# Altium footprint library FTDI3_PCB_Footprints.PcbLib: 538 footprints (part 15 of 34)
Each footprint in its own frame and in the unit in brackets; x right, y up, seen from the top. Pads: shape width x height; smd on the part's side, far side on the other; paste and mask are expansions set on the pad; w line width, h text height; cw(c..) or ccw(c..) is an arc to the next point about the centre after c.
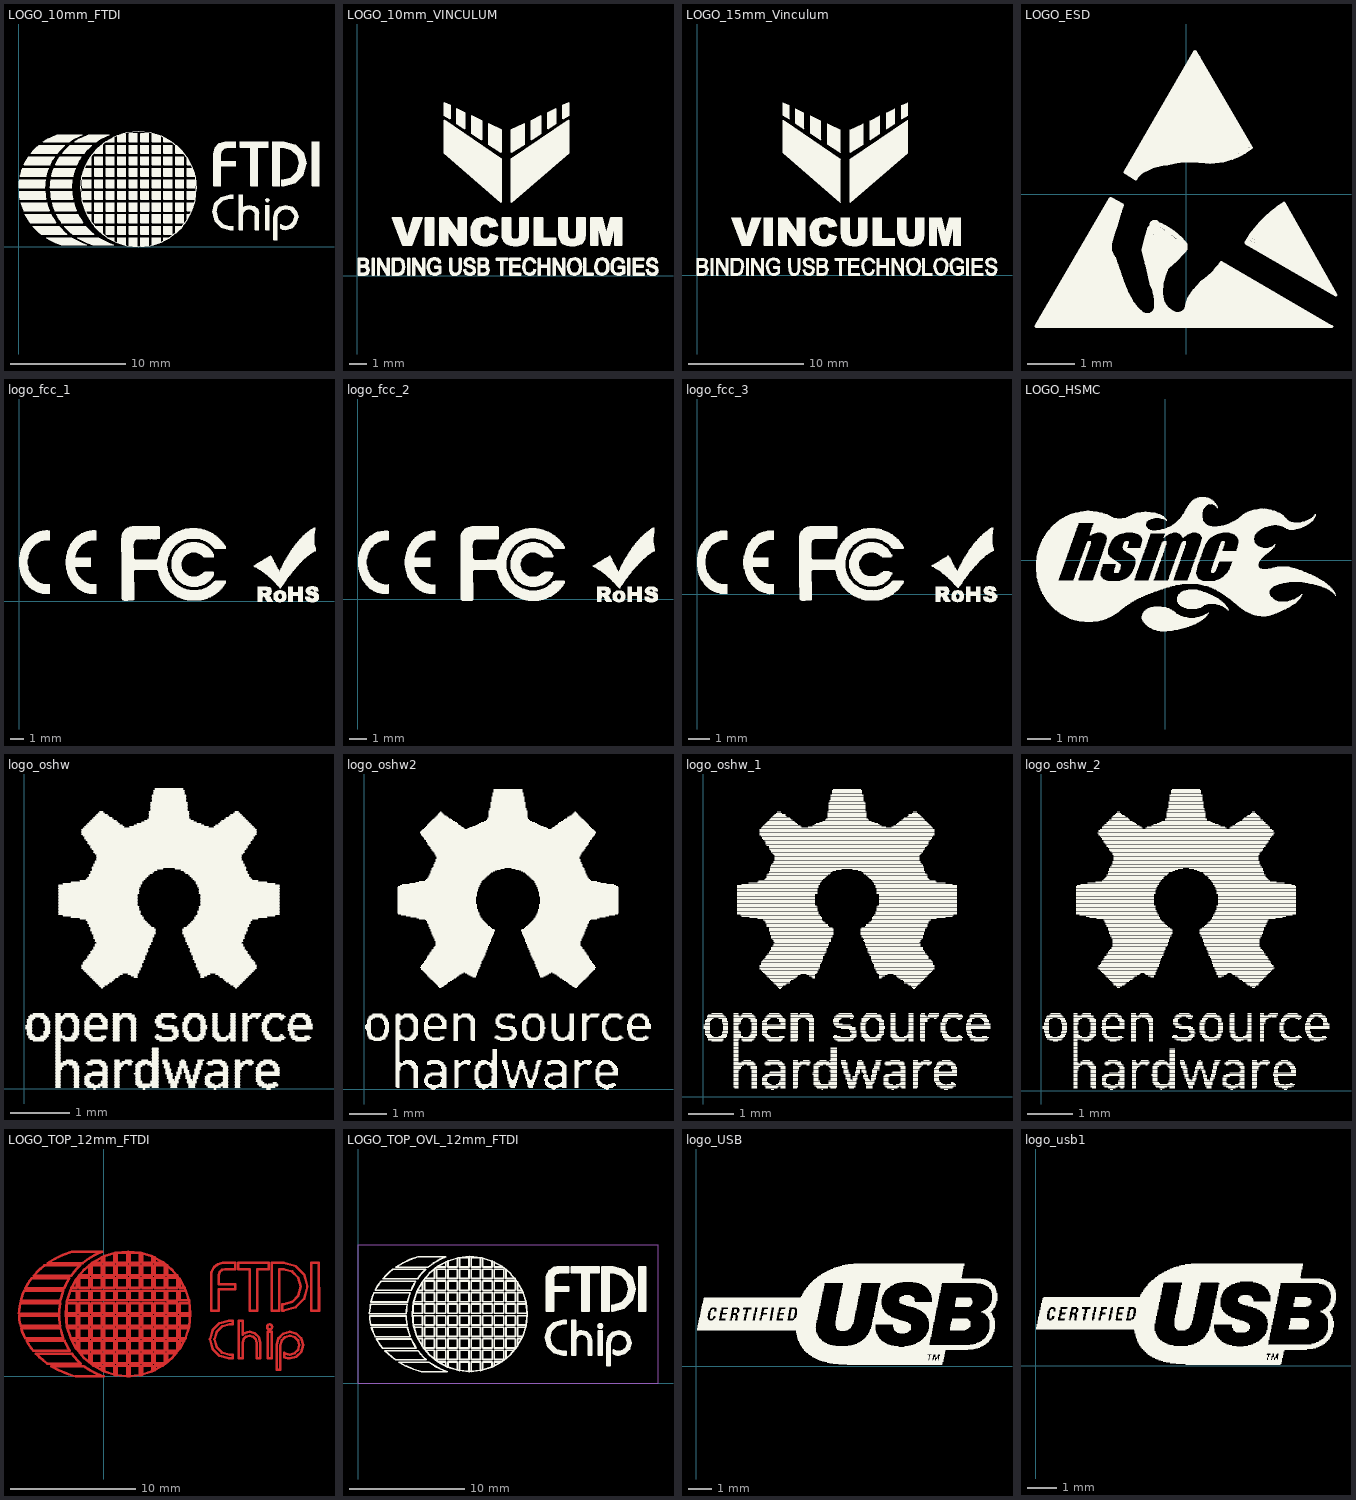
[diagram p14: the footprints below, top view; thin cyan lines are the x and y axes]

## LOGO_10mm_FTDI [mm]
Top Overlay:
  drawing of 816 lines, arcs and shapes, not listed

## LOGO_10mm_VINCULUM [mm]
Top Overlay:
  drawing of 1161 lines, arcs and shapes, not listed

## LOGO_15mm_Vinculum [mm] "Logo, Vinculum, 15mm Height"
Top Overlay:
  drawing of 1150 lines, arcs and shapes, not listed

## LOGO_ESD [mm]
Top Overlay:
  drawing of 1029 lines, arcs and shapes, not listed

## logo_fcc_1 [mm]
Top Overlay:
  drawing of 1453 lines, arcs and shapes, not listed

## logo_fcc_2 [mm]
Top Overlay:
  drawing of 1141 lines, arcs and shapes, not listed

## logo_fcc_3 [mm]
Top Overlay:
  drawing of 910 lines, arcs and shapes, not listed

## LOGO_HSMC [mm]
Top Overlay:
  drawing of 2170 lines, arcs and shapes, not listed

## logo_oshw [mm]
Top Overlay:
  drawing of 812 lines, arcs and shapes, not listed

## logo_oshw2 [mm]
Top Overlay:
  drawing of 1256 lines, arcs and shapes, not listed

## logo_oshw_1 [mm]
Top Overlay:
  drawing of 1060 lines, arcs and shapes, not listed

## logo_oshw_2 [mm]
Top Overlay:
  drawing of 1071 lines, arcs and shapes, not listed

## LOGO_TOP_12mm_FTDI [mm]
Top Layer:
  lines w0.2: -2.955,4.121 -2.955,4.857 -2.154,4.857 -2.154,4.059 ; -2.955,5.795 -2.955,5.062 -2.154,5.062 -2.154,5.867 -2.944,5.867 ; -2.944,4.061 -2.154,4.059 ; -2.908,6.072 -2.154,6.072 -2.154,6.869 -2.656,6.869 ; -2.899,3.861 -2.154,3.858 -2.154,3.053 -2.62,3.053 ; -2.57,7.07 -2.154,7.07 -2.154,7.809 ; -2.527,2.855 -2.154,2.855 -2.154,2.208 ; -2.174,4.062 -2.168,4.061 -2.16,4.059 -2.154,4.059 ; -1.951,8.082 -1.147,8.082 -1.147,8.88 ; -1.886,1.85 -1.147,1.85 -1.147,1.121 ; -0.898,9.084 -0.141,9.084 -0.141,9.513 ; -0.765,0.843 -0.141,0.843 -0.141,0.496 ; 0.056,0.409 0.056,0.843 0.863,0.843 0.863,0.151 ; 0.056,9.601 0.056,9.084 0.863,9.084 0.863,9.859 ; 1.062,0.105 1.062,0.843 1.868,0.843 1.868,0.024 ; 2.068,0.026 2.068,0.843 2.874,0.843 2.874,0.11 ; 3.076,0.151 3.076,0.843 3.879,0.843 3.879,0.409 ; 3.076,9.859 3.076,9.084 3.879,9.084 3.879,9.595 ; 4.073,0.498 4.073,0.843 4.686,0.843 ; 4.073,9.508 4.073,9.084 4.809,9.084 ; 5.079,1.13 5.079,1.85 5.8,1.85 ; 5.079,8.88 5.079,8.082 5.872,8.082 ; 6.081,2.22 6.081,2.855 6.446,2.855 ; 6.081,7.791 6.081,7.07 6.488,7.07 ; 6.542,3.053 6.081,3.053 6.081,3.858 6.806,3.858 ; 6.575,6.869 6.081,6.869 6.081,6.072 6.824,6.072 ; 6.846,4.059 6.081,4.059 6.081,4.857 6.891,4.857 6.891,4.326 ; 6.847,5.867 6.081,5.867 6.081,5.062 6.891,5.062 6.891,5.694 ; 9.197,8.111 9.265,8.347 9.447,8.515 9.705,8.579 10.507,8.579 10.508,9.084 9.513,9.086 9.139,8.979 8.822,8.727 8.627,8.382 8.611,8.316 8.601,8.25 8.597,8.187 8.6,5.263 9.202,5.263 9.202,6.974 10.507,6.974 10.507,7.375 9.202,7.375 9.197,8.111 ; 9.197,8.111 9.197,8.11 9.197,8.113 9.197,8.111 ; 10.807,1.445 10.818,1.445 10.807,1.445 ; 10.807,1.445 10.807,4.462 11.111,4.462 11.111,3.35 11.276,3.461 11.464,3.533 11.662,3.559 12.094,3.442 12.401,3.137 12.518,2.706 12.518,1.445 12.216,1.445 12.216,2.709 12.14,2.986 11.941,3.181 11.662,3.256 11.384,3.182 11.186,2.987 11.111,2.71 11.111,1.445 10.807,1.445 ; 14.387,9.085 13.421,9.077 13.421,5.261 14.026,5.264 14.026,8.58 14.389,8.579 15.066,8.388 15.551,7.887 15.737,7.18 15.553,6.47 15.072,5.965 14.396,5.772 14.29,5.772 14.29,5.27 14.393,5.27 15.348,5.532 16.028,6.219 16.287,7.183 16.026,8.143 15.343,8.825 14.386,9.085 ; 14.386,9.085 14.387,9.085 ; 14.387,9.085 14.387,9.085 ; 14.387,9.085 14.387,9.085 ; -6.764,5.041 -6.758,5.041 -6.746,5.041 -6.739,5.041 -3.559,5.027 -3.546,5.305 -3.517,5.588 -3.477,5.853 -6.657,5.853 -6.696,5.596 -6.742,5.311 -6.764,5.041 ; -6.742,4.841 -6.726,4.571 -6.686,4.303 -6.636,4.047 -3.488,4.047 -3.525,4.298 -3.556,4.576 -3.567,4.841 -6.742,4.841 ; -6.624,6.049 -6.554,6.314 -6.457,6.592 -6.353,6.857 -3.227,6.857 -3.316,6.592 -3.4,6.314 -3.461,6.049 -6.624,6.049 ; -6.576,3.846 -6.49,3.577 -6.386,3.294 -6.267,3.04 -3.211,3.04 -3.304,3.294 -3.385,3.577 -3.45,3.846 -6.576,3.846 ; -6.254,7.06 -6.107,7.326 -5.93,7.603 -5.748,7.854 -2.744,7.854 -2.886,7.603 -3.02,7.326 -3.136,7.06 -6.254,7.06 ; -6.158,2.839 -6.003,2.572 -5.808,2.291 -5.605,2.037 -2.694,2.037 -2.851,2.295 -2.998,2.567 -3.126,2.839 -6.158,2.839 ; -5.583,8.051 -5.328,8.334 -5.034,8.62 -4.73,8.875 -1.883,8.875 -2.134,8.621 -2.377,8.336 -2.588,8.055 -5.583,8.051 ; -5.42,1.827 -2.548,1.827 -2.322,1.544 -2.083,1.275 -1.831,1.031 -4.502,1.031 -4.818,1.279 -5.138,1.552 -5.42,1.827 ; -4.473,9.062 -3.878,9.419 -3.224,9.732 -2.546,9.979 -0.131,9.979 -0.676,9.732 -1.197,9.419 -1.676,9.062 -4.473,9.062 ; -4.185,0.821 -3.576,0.49 -2.919,0.208 -2.243,0 0,0 -0.545,0.213 -1.093,0.498 -1.581,0.821 -4.185,0.821 ; -3.035,5 -2.934,6.002 -2.643,6.936 -2.182,7.782 -1.573,8.52 -0.835,9.13 0.012,9.59 0.946,9.881 1.948,9.983 2.951,9.881 3.886,9.59 4.732,9.13 5.47,8.52 6.079,7.782 6.54,6.936 6.831,6.002 6.932,5 6.831,3.997 6.54,3.062 6.079,2.216 5.47,1.478 4.732,0.868 3.886,0.408 2.951,0.117 1.948,0.015 0.946,0.117 0.012,0.408 -0.835,0.868 -1.573,1.478 -2.182,2.216 -2.643,3.062 -2.934,3.997 -3.035,5 ; -1.951,2.056 -1.951,2.855 -1.143,2.855 -1.143,2.056 -1.951,2.056 ; -1.951,3.059 -1.951,3.858 -1.143,3.858 -1.143,3.059 -1.951,3.059 ; -1.951,4.058 -1.951,4.857 -1.143,4.857 -1.143,4.058 -1.951,4.058 ; -1.951,5.068 -1.951,5.867 -1.143,5.867 -1.143,5.068 -1.951,5.068 ; -1.951,6.071 -1.951,6.869 -1.143,6.869 -1.143,6.071 -1.951,6.071 ; -1.951,7.075 -1.951,7.875 -1.143,7.875 -1.143,7.075 -1.951,7.075 ; -0.949,1.051 -0.949,1.85 -0.141,1.85 -0.141,1.051 -0.949,1.051 ; -0.949,2.056 -0.949,2.855 -0.141,2.855 -0.141,2.056 -0.949,2.056 ; -0.949,3.059 -0.949,3.858 -0.141,3.858 -0.141,3.059 -0.949,3.059 ; -0.949,4.058 -0.949,4.857 -0.141,4.857 -0.141,4.058 -0.949,4.058 ; -0.949,5.068 -0.949,5.867 -0.141,5.867 -0.141,5.068 -0.949,5.068 ; -0.949,6.071 -0.949,6.869 -0.141,6.869 -0.141,6.071 -0.949,6.071 ; -0.949,7.075 -0.949,7.875 -0.141,7.875 -0.141,7.075 -0.949,7.075 ; -0.949,8.082 -0.949,8.88 -0.141,8.88 -0.141,8.082 -0.949,8.082 ; 0.056,1.051 0.056,1.85 0.865,1.85 0.865,1.051 0.056,1.051 ; 0.056,2.056 0.056,2.855 0.865,2.855 0.865,2.056 0.056,2.056 ; 0.056,3.059 0.056,3.858 0.865,3.858 0.865,3.059 0.056,3.059 ; 0.056,4.058 0.056,4.857 0.865,4.857 0.865,4.058 0.056,4.058 ; 0.056,5.068 0.056,5.867 0.865,5.867 0.865,5.068 0.056,5.068 ; 0.056,6.071 0.056,6.869 0.865,6.869 0.865,6.071 0.056,6.071 ; 0.056,7.075 0.056,7.875 0.865,7.875 0.865,7.075 0.056,7.075 ; 0.056,8.082 0.056,8.88 0.865,8.88 0.865,8.082 0.056,8.082 ; 1.062,1.051 1.062,1.85 1.869,1.85 1.869,1.051 1.062,1.051 ; 1.062,2.056 1.062,2.855 1.869,2.855 1.869,2.056 1.062,2.056 ; 1.062,3.059 1.062,3.858 1.869,3.858 1.869,3.059 1.062,3.059 ; 1.062,4.058 1.062,4.857 1.869,4.857 1.869,4.058 1.062,4.058 ; 1.062,5.068 1.062,5.867 1.869,5.867 1.869,5.068 1.062,5.068 ; 1.062,6.071 1.062,6.869 1.869,6.869 1.869,6.071 1.062,6.071 ; 1.062,7.075 1.062,7.875 1.869,7.875 1.869,7.075 1.062,7.075 ; 1.062,8.082 1.062,8.88 1.869,8.88 1.869,8.082 1.062,8.082 ; 1.062,9.084 1.062,9.882 1.869,9.882 1.869,9.084 1.062,9.084 ; 2.068,1.051 2.068,1.85 2.876,1.85 2.876,1.051 2.068,1.051 ; 2.068,2.056 2.068,2.855 2.876,2.855 2.876,2.056 2.068,2.056 ; 2.068,3.059 2.068,3.858 2.876,3.858 2.876,3.059 2.068,3.059 ; 2.068,4.058 2.068,4.857 2.876,4.857 2.876,4.058 2.068,4.058 ; 2.068,5.068 2.068,5.867 2.876,5.867 2.876,5.068 2.068,5.068 ; 2.068,6.071 2.068,6.869 2.876,6.869 2.876,6.071 2.068,6.071 ; 2.068,7.075 2.068,7.875 2.876,7.875 2.876,7.075 2.068,7.075 ; 2.068,8.082 2.068,8.88 2.876,8.88 2.876,8.082 2.068,8.082 ; 2.068,9.084 2.068,9.882 2.876,9.882 2.876,9.084 2.068,9.084 ; 3.076,1.051 3.076,1.85 3.883,1.85 3.883,1.051 3.076,1.051 ; 3.076,2.056 3.076,2.855 3.883,2.855 3.883,2.056 3.076,2.056 ; 3.076,3.059 3.076,3.858 3.883,3.858 3.883,3.059 3.076,3.059 ; 3.076,4.058 3.076,4.857 3.883,4.857 3.883,4.058 3.076,4.058 ; 3.076,5.068 3.076,5.867 3.883,5.867 3.883,5.068 3.076,5.068 ; 3.076,6.071 3.076,6.869 3.883,6.869 3.883,6.071 3.076,6.071 ; 3.076,7.075 3.076,7.875 3.883,7.875 3.883,7.075 3.076,7.075 ; 3.076,8.082 3.076,8.88 3.883,8.88 3.883,8.082 3.076,8.082 ; 4.073,1.051 4.073,1.85 4.88,1.85 4.88,1.051 4.073,1.051 ; 4.073,2.056 4.073,2.855 4.88,2.855 4.88,2.056 4.073,2.056 ; 4.073,3.059 4.073,3.858 4.88,3.858 4.88,3.059 4.073,3.059 ; 4.073,4.058 4.073,4.857 4.88,4.857 4.88,4.058 4.073,4.058 ; 4.073,5.068 4.073,5.867 4.88,5.867 4.88,5.068 4.073,5.068 ; 4.073,6.071 4.073,6.869 4.88,6.869 4.88,6.071 4.073,6.071 ; 4.073,7.075 4.073,7.875 4.88,7.875 4.88,7.075 4.073,7.075 ; 4.073,8.082 4.073,8.88 4.88,8.88 4.88,8.082 4.073,8.082 ; 5.079,2.056 5.079,2.855 5.887,2.855 5.887,2.056 5.079,2.056 ; 5.079,3.059 5.079,3.858 5.887,3.858 5.887,3.059 5.079,3.059 ; 5.079,4.058 5.079,4.857 5.887,4.857 5.887,4.058 5.079,4.058 ; 5.079,5.068 5.079,5.867 5.887,5.867 5.887,5.068 5.079,5.068 ; 5.079,6.066 5.079,6.865 5.887,6.865 5.887,6.066 5.079,6.066 ; 5.079,7.075 5.079,7.875 5.887,7.875 5.887,7.075 5.079,7.075 ; 8.497,2.954 8.703,2.194 9.244,1.652 10.005,1.445 10.307,1.445 10.307,1.75 10.061,1.75 9.455,1.914 9.022,2.347 8.857,2.954 9.023,3.561 9.458,3.993 10.066,4.158 10.307,4.158 10.307,4.463 10.002,4.463 9.242,4.256 8.702,3.715 8.497,2.954 ; 10.769,8.578 10.769,9.085 13.181,9.085 13.181,8.578 12.276,8.579 12.278,5.261 11.669,5.261 11.673,8.578 10.769,8.578 ; 13.066,3.96 13.093,4.06 13.165,4.13 13.265,4.157 13.366,4.13 13.438,4.06 13.465,3.96 13.438,3.858 13.366,3.786 13.265,3.759 13.165,3.786 13.093,3.858 13.066,3.96 ; 13.117,1.445 13.117,3.56 13.423,3.56 13.423,1.445 13.117,1.445 ; 13.821,0.538 14.13,0.538 14.13,2.502 14.233,2.881 14.504,3.151 14.883,3.255 15.262,3.151 15.533,2.881 15.636,2.501 15.533,2.122 15.262,1.852 14.883,1.749 14.719,1.768 14.561,1.822 14.419,1.909 14.419,1.552 14.566,1.495 14.72,1.458 14.878,1.445 15.411,1.589 15.79,1.969 15.934,2.502 15.79,3.034 15.411,3.414 14.878,3.559 14.345,3.414 13.966,3.034 13.821,2.502 13.821,0.538 ; 16.603,5.268 16.603,9.085 17.207,9.085 17.209,5.268 16.603,5.268

## LOGO_TOP_OVL_12mm_FTDI [mm]
Top Overlay:
  drawing of 586 lines, arcs and shapes, not listed
M15_Country_Yard:
  lines w0.1: 0,0 26.02,0 26.02,12.01 0,12.01 0,0

## logo_USB [mm]
Top Overlay:
  drawing of 904 lines, arcs and shapes, not listed

## logo_usb1 [mm]
Top Overlay:
  drawing of 724 lines, arcs and shapes, not listed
